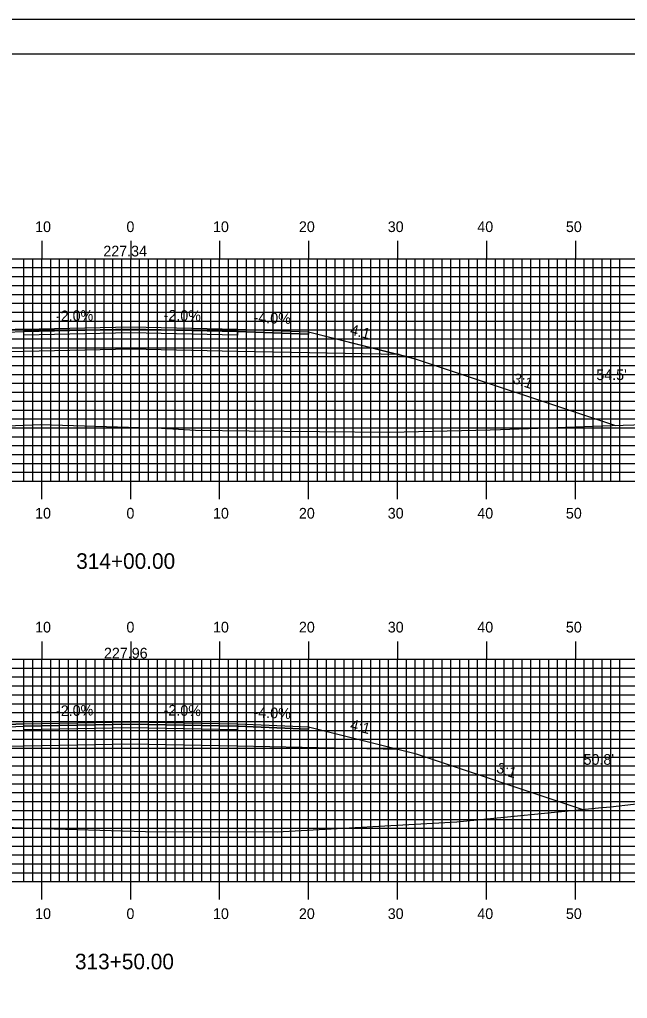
# Model space of a CAD drawing. Extents: x 1818850 to 1819194, y 442591 to 442811.
# Drawn here: x 1819003.7 to 1819072, y 442700.5 to 442810.5 of the extents above; entities that cross this region are included whole.
import ezdxf

# ---------------------------------------------------------------- set-up
doc = ezdxf.new("R2010")
doc.units = 0
for name, color, linetype in [('ANNOTATION', 7, 'Continuous'), ('BORDER', 7, 'Continuous'), ('D_Roadway_Centerline', 7, 'Continuous'), ('D_Roadway_Centerline_Text', 7, 'Continuous'), ('D_Roadway_Edge_Shoulder', 7, 'Continuous'), ('D_Roadway_Edge_TW', 7, 'Continuous'), ('D_Roadway_Pavement', 7, 'Continuous'), ('D_Roadway_SlopeLines', 7, 'Continuous'), ('D_Roadway_SubGrade', 7, 'Continuous'), ('D_Text_Standard', 7, 'Continuous'), ('H_V ANNOTATION', 7, 'Continuous'), ('MAJOR', 7, 'Continuous'), ('MINOR', 7, 'Continuous'), ('PLOT BOUNDARY', 7, 'Continuous'), ('S_Roadway_Centerline', 7, 'Continuous')]:
    doc.layers.add(name, color=color, linetype=linetype)

msp = doc.modelspace()

# ---------------------------------------------------------------- linework, layer by layer
at = {"layer": 'BORDER'}
msp.add_lwpolyline([(1818866.55, 442596.67), (1819186.55, 442596.67), (1819186.55, 442806.67), (1818866.55, 442806.67)], close=True, dxfattribs=at)
at = {"layer": 'D_Roadway_Centerline'}
for points in [[(1818961.68, 442764.95), (1818984.15, 442772.44), (1818985.98, 442772.9), (1818996.15, 442775.44), (1819004.15, 442775.76), (1819016.15, 442776), (1819028.15, 442775.76), (1819036.15, 442775.44), (1819046.33, 442772.9), (1819048.15, 442772.44), (1819070.66, 442764.94)], [(1818960.21, 442720.09), (1818984.15, 442728.07), (1818985.98, 442728.52), (1818996.15, 442731.07), (1819004.15, 442731.39), (1819016.15, 442731.63), (1819028.15, 442731.39), (1819036.15, 442731.07), (1819046.33, 442728.52), (1819048.15, 442728.07), (1819066.99, 442721.79)]]:
    msp.add_lwpolyline(points, dxfattribs=at)
at = {"layer": 'D_Roadway_Edge_Shoulder'}
for points in [[(1819004.15, 442775.76), (1818996.15, 442775.44), (1818996.15, 442775.19), (1819004.15, 442775.51)], [(1819028.15, 442775.76), (1819036.15, 442775.44), (1819036.15, 442775.19), (1819028.15, 442775.51)], [(1819004.15, 442731.39), (1818996.15, 442731.07), (1818996.15, 442730.82), (1819004.15, 442731.14)], [(1819028.15, 442731.39), (1819036.15, 442731.07), (1819036.15, 442730.82), (1819028.15, 442731.14)]]:
    msp.add_lwpolyline(points, close=True, dxfattribs=at)
at = {"layer": 'D_Roadway_Edge_TW'}
for points in [[(1819004.15, 442775.51), (1819004.15, 442775.76), (1819016.15, 442776), (1819028.15, 442775.76), (1819028.15, 442775.51), (1819016.15, 442775.75)], [(1819004.15, 442731.14), (1819004.15, 442731.39), (1819016.15, 442731.63), (1819028.15, 442731.39), (1819028.15, 442731.14), (1819016.15, 442731.38)]]:
    msp.add_lwpolyline(points, close=True, dxfattribs=at)
at = {"layer": 'D_Roadway_Pavement'}
for points in [[(1819004.15, 442775.09), (1819004.15, 442775.51), (1819016.15, 442775.75), (1819028.15, 442775.51), (1819028.15, 442775.09), (1819016.15, 442775.33)], [(1819004.15, 442730.72), (1819004.15, 442731.14), (1819016.15, 442731.38), (1819028.15, 442731.14), (1819028.15, 442730.72), (1819016.15, 442730.96)]]:
    msp.add_lwpolyline(points, close=True, dxfattribs=at)
at = {"layer": 'D_Roadway_SlopeLines'}
for points in [[(1819036.15, 442775.44), (1819048.15, 442772.44), (1819070.66, 442764.94)], [(1819036.15, 442731.07), (1819048.15, 442728.07), (1819066.99, 442721.79)]]:
    msp.add_lwpolyline(points, dxfattribs=at)
at = {"layer": 'D_Roadway_SubGrade'}
for points in [[(1819004.15, 442773.26), (1818985.98, 442772.9), (1818996.15, 442775.44), (1818996.15, 442775.19), (1819004.15, 442775.51), (1819016.15, 442775.75), (1819028.15, 442775.51), (1819036.15, 442775.19), (1819036.15, 442775.44), (1819046.33, 442772.9), (1819028.15, 442773.26), (1819016.15, 442773.5)], [(1819004.15, 442728.89), (1818985.98, 442728.52), (1818996.15, 442731.07), (1818996.15, 442730.82), (1819004.15, 442731.14), (1819016.15, 442731.38), (1819028.15, 442731.14), (1819036.15, 442730.82), (1819036.15, 442731.07), (1819046.33, 442728.52), (1819028.15, 442728.89), (1819016.15, 442729.13)]]:
    msp.add_lwpolyline(points, close=True, dxfattribs=at)
at = {"layer": 'MAJOR'}
for p, q in [((1819006.15, 442785.67), (1819006.15, 442783.67)), ((1819016.15, 442785.67), (1819016.15, 442783.67)), ((1819026.15, 442785.67), (1819026.15, 442783.67)), ((1819036.15, 442785.67), (1819036.15, 442783.67)), ((1819046.15, 442785.67), (1819046.15, 442783.67)), ((1819056.15, 442785.67), (1819056.15, 442783.67)), ((1819066.15, 442785.67), (1819066.15, 442783.67)), ((1818876.15, 442783.67), (1819156.15, 442783.67)), ((1818876.15, 442783.67), (1819156.15, 442783.67)), ((1819006.15, 442758.67), (1819006.15, 442783.67)), ((1819016.15, 442758.67), (1819016.15, 442783.67)), ((1819026.15, 442758.67), (1819026.15, 442783.67)), ((1819036.15, 442758.67), (1819036.15, 442783.67)), ((1819046.15, 442758.67), (1819046.15, 442783.67)), ((1819056.15, 442758.67), (1819056.15, 442783.67)), ((1819066.15, 442758.67), (1819066.15, 442783.67)), ((1818876.15, 442778.67), (1819156.15, 442778.67)), ((1818876.15, 442773.67), (1819156.15, 442773.67)), ((1818876.15, 442768.67), (1819156.15, 442768.67)), ((1818876.15, 442763.67), (1819156.15, 442763.67)), ((1818876.15, 442758.67), (1819156.15, 442758.67)), ((1818876.15, 442758.67), (1819156.15, 442758.67)), ((1819006.15, 442756.66), (1819006.15, 442758.67)), ((1819016.15, 442756.66), (1819016.15, 442758.67)), ((1819026.15, 442756.66), (1819026.15, 442758.67)), ((1819036.15, 442756.66), (1819036.15, 442758.67)), ((1819046.15, 442756.66), (1819046.15, 442758.67)), ((1819056.15, 442756.66), (1819056.15, 442758.67)), ((1819066.15, 442756.66), (1819066.15, 442758.67)), ((1819006.15, 442740.67), (1819006.15, 442738.67)), ((1819016.15, 442740.67), (1819016.15, 442738.67)), ((1819026.15, 442740.67), (1819026.15, 442738.67)), ((1819036.15, 442740.67), (1819036.15, 442738.67)), ((1819046.15, 442740.67), (1819046.15, 442738.67)), ((1819056.15, 442740.67), (1819056.15, 442738.67)), ((1819066.15, 442740.67), (1819066.15, 442738.67)), ((1818876.15, 442738.67), (1819156.15, 442738.67)), ((1818876.15, 442738.67), (1819156.15, 442738.67)), ((1819006.15, 442713.67), (1819006.15, 442738.67)), ((1819016.15, 442713.67), (1819016.15, 442738.67)), ((1819026.15, 442713.67), (1819026.15, 442738.67)), ((1819036.15, 442713.67), (1819036.15, 442738.67)), ((1819046.15, 442713.67), (1819046.15, 442738.67)), ((1819056.15, 442713.67), (1819056.15, 442738.67)), ((1819066.15, 442713.67), (1819066.15, 442738.67)), ((1818876.15, 442733.67), (1819156.15, 442733.67)), ((1818876.15, 442728.67), (1819156.15, 442728.67)), ((1818876.15, 442723.67), (1819156.15, 442723.67)), ((1818876.15, 442718.67), (1819156.15, 442718.67)), ((1818876.15, 442713.67), (1819156.15, 442713.67)), ((1818876.15, 442713.67), (1819156.15, 442713.67)), ((1819006.15, 442711.66), (1819006.15, 442713.67)), ((1819016.15, 442711.66), (1819016.15, 442713.67)), ((1819026.15, 442711.66), (1819026.15, 442713.67)), ((1819036.15, 442711.66), (1819036.15, 442713.67)), ((1819046.15, 442711.66), (1819046.15, 442713.67)), ((1819056.15, 442711.66), (1819056.15, 442713.67)), ((1819066.15, 442711.66), (1819066.15, 442713.67))]:
    msp.add_line(p, q, dxfattribs=at)
at = {"layer": 'MINOR'}
for p, q in [((1819004.15, 442758.67), (1819004.15, 442783.67)), ((1819005.15, 442758.67), (1819005.15, 442783.67)), ((1819007.15, 442758.67), (1819007.15, 442783.67)), ((1819008.15, 442758.67), (1819008.15, 442783.67)), ((1819009.15, 442758.67), (1819009.15, 442783.67)), ((1819010.15, 442758.67), (1819010.15, 442783.67)), ((1819011.15, 442758.67), (1819011.15, 442783.67)), ((1819012.15, 442758.67), (1819012.15, 442783.67)), ((1819013.15, 442758.67), (1819013.15, 442783.67)), ((1819014.15, 442758.67), (1819014.15, 442783.67)), ((1819015.15, 442758.67), (1819015.15, 442783.67)), ((1819017.15, 442758.67), (1819017.15, 442783.67)), ((1819018.15, 442758.67), (1819018.15, 442783.67)), ((1819019.15, 442758.67), (1819019.15, 442783.67)), ((1819020.15, 442758.67), (1819020.15, 442783.67)), ((1819021.15, 442758.67), (1819021.15, 442783.67)), ((1819022.15, 442758.67), (1819022.15, 442783.67)), ((1819023.15, 442758.67), (1819023.15, 442783.67)), ((1819024.15, 442758.67), (1819024.15, 442783.67)), ((1819025.15, 442758.67), (1819025.15, 442783.67)), ((1819027.15, 442758.67), (1819027.15, 442783.67)), ((1819028.15, 442758.67), (1819028.15, 442783.67)), ((1819029.15, 442758.67), (1819029.15, 442783.67)), ((1819030.15, 442758.67), (1819030.15, 442783.67)), ((1819031.15, 442758.67), (1819031.15, 442783.67)), ((1819032.15, 442758.67), (1819032.15, 442783.67)), ((1819033.15, 442758.67), (1819033.15, 442783.67)), ((1819034.15, 442758.67), (1819034.15, 442783.67)), ((1819035.15, 442758.67), (1819035.15, 442783.67)), ((1819037.15, 442758.67), (1819037.15, 442783.67)), ((1819038.15, 442758.67), (1819038.15, 442783.67)), ((1819039.15, 442758.67), (1819039.15, 442783.67)), ((1819040.15, 442758.67), (1819040.15, 442783.67)), ((1819041.15, 442758.67), (1819041.15, 442783.67)), ((1819042.15, 442758.67), (1819042.15, 442783.67)), ((1819043.15, 442758.67), (1819043.15, 442783.67)), ((1819044.15, 442758.67), (1819044.15, 442783.67)), ((1819045.15, 442758.67), (1819045.15, 442783.67)), ((1819047.15, 442758.67), (1819047.15, 442783.67)), ((1819048.15, 442758.67), (1819048.15, 442783.67)), ((1819049.15, 442758.67), (1819049.15, 442783.67)), ((1819050.15, 442758.67), (1819050.15, 442783.67)), ((1819051.15, 442758.67), (1819051.15, 442783.67)), ((1819052.15, 442758.67), (1819052.15, 442783.67)), ((1819053.15, 442758.67), (1819053.15, 442783.67)), ((1819054.15, 442758.67), (1819054.15, 442783.67)), ((1819055.15, 442758.67), (1819055.15, 442783.67)), ((1819057.15, 442758.67), (1819057.15, 442783.67)), ((1819058.15, 442758.67), (1819058.15, 442783.67)), ((1819059.15, 442758.67), (1819059.15, 442783.67)), ((1819060.15, 442758.67), (1819060.15, 442783.67)), ((1819061.15, 442758.67), (1819061.15, 442783.67)), ((1819062.15, 442758.67), (1819062.15, 442783.67)), ((1819063.15, 442758.67), (1819063.15, 442783.67)), ((1819064.15, 442758.67), (1819064.15, 442783.67)), ((1819065.15, 442758.67), (1819065.15, 442783.67)), ((1819067.15, 442758.67), (1819067.15, 442783.67)), ((1819068.15, 442758.67), (1819068.15, 442783.67)), ((1819069.15, 442758.67), (1819069.15, 442783.67)), ((1819070.15, 442758.67), (1819070.15, 442783.67)), ((1819071.15, 442758.67), (1819071.15, 442783.67)), ((1818876.15, 442782.67), (1819156.15, 442782.67)), ((1818876.15, 442781.67), (1819156.15, 442781.67)), ((1818876.15, 442780.67), (1819156.15, 442780.67)), ((1818876.15, 442779.67), (1819156.15, 442779.67)), ((1818876.15, 442777.67), (1819156.15, 442777.67)), ((1818876.15, 442776.67), (1819156.15, 442776.67)), ((1818876.15, 442775.67), (1819156.15, 442775.67)), ((1818876.15, 442774.67), (1819156.15, 442774.67)), ((1818876.15, 442772.67), (1819156.15, 442772.67)), ((1818876.15, 442771.67), (1819156.15, 442771.67)), ((1818876.15, 442770.67), (1819156.15, 442770.67)), ((1818876.15, 442769.67), (1819156.15, 442769.67)), ((1818876.15, 442767.67), (1819156.15, 442767.67)), ((1818876.15, 442766.67), (1819156.15, 442766.67)), ((1818876.15, 442765.67), (1819156.15, 442765.67)), ((1818876.15, 442764.67), (1819156.15, 442764.67)), ((1818876.15, 442762.67), (1819156.15, 442762.67)), ((1818876.15, 442761.67), (1819156.15, 442761.67)), ((1818876.15, 442760.67), (1819156.15, 442760.67)), ((1818876.15, 442759.67), (1819156.15, 442759.67)), ((1819004.15, 442713.67), (1819004.15, 442738.67)), ((1819005.15, 442713.67), (1819005.15, 442738.67)), ((1819007.15, 442713.67), (1819007.15, 442738.67)), ((1819008.15, 442713.67), (1819008.15, 442738.67)), ((1819009.15, 442713.67), (1819009.15, 442738.67)), ((1819010.15, 442713.67), (1819010.15, 442738.67)), ((1819011.15, 442713.67), (1819011.15, 442738.67)), ((1819012.15, 442713.67), (1819012.15, 442738.67)), ((1819013.15, 442713.67), (1819013.15, 442738.67)), ((1819014.15, 442713.67), (1819014.15, 442738.67)), ((1819015.15, 442713.67), (1819015.15, 442738.67)), ((1819017.15, 442713.67), (1819017.15, 442738.67)), ((1819018.15, 442713.67), (1819018.15, 442738.67)), ((1819019.15, 442713.67), (1819019.15, 442738.67)), ((1819020.15, 442713.67), (1819020.15, 442738.67)), ((1819021.15, 442713.67), (1819021.15, 442738.67)), ((1819022.15, 442713.67), (1819022.15, 442738.67)), ((1819023.15, 442713.67), (1819023.15, 442738.67)), ((1819024.15, 442713.67), (1819024.15, 442738.67)), ((1819025.15, 442713.67), (1819025.15, 442738.67)), ((1819027.15, 442713.67), (1819027.15, 442738.67)), ((1819028.15, 442713.67), (1819028.15, 442738.67)), ((1819029.15, 442713.67), (1819029.15, 442738.67)), ((1819030.15, 442713.67), (1819030.15, 442738.67)), ((1819031.15, 442713.67), (1819031.15, 442738.67)), ((1819032.15, 442713.67), (1819032.15, 442738.67)), ((1819033.15, 442713.67), (1819033.15, 442738.67)), ((1819034.15, 442713.67), (1819034.15, 442738.67)), ((1819035.15, 442713.67), (1819035.15, 442738.67)), ((1819037.15, 442713.67), (1819037.15, 442738.67)), ((1819038.15, 442713.67), (1819038.15, 442738.67)), ((1819039.15, 442713.67), (1819039.15, 442738.67)), ((1819040.15, 442713.67), (1819040.15, 442738.67)), ((1819041.15, 442713.67), (1819041.15, 442738.67)), ((1819042.15, 442713.67), (1819042.15, 442738.67)), ((1819043.15, 442713.67), (1819043.15, 442738.67)), ((1819044.15, 442713.67), (1819044.15, 442738.67)), ((1819045.15, 442713.67), (1819045.15, 442738.67)), ((1819047.15, 442713.67), (1819047.15, 442738.67)), ((1819048.15, 442713.67), (1819048.15, 442738.67)), ((1819049.15, 442713.67), (1819049.15, 442738.67)), ((1819050.15, 442713.67), (1819050.15, 442738.67)), ((1819051.15, 442713.67), (1819051.15, 442738.67)), ((1819052.15, 442713.67), (1819052.15, 442738.67)), ((1819053.15, 442713.67), (1819053.15, 442738.67)), ((1819054.15, 442713.67), (1819054.15, 442738.67)), ((1819055.15, 442713.67), (1819055.15, 442738.67)), ((1819057.15, 442713.67), (1819057.15, 442738.67)), ((1819058.15, 442713.67), (1819058.15, 442738.67)), ((1819059.15, 442713.67), (1819059.15, 442738.67)), ((1819060.15, 442713.67), (1819060.15, 442738.67)), ((1819061.15, 442713.67), (1819061.15, 442738.67)), ((1819062.15, 442713.67), (1819062.15, 442738.67)), ((1819063.15, 442713.67), (1819063.15, 442738.67)), ((1819064.15, 442713.67), (1819064.15, 442738.67)), ((1819065.15, 442713.67), (1819065.15, 442738.67)), ((1819067.15, 442713.67), (1819067.15, 442738.67)), ((1819068.15, 442713.67), (1819068.15, 442738.67)), ((1819069.15, 442713.67), (1819069.15, 442738.67)), ((1819070.15, 442713.67), (1819070.15, 442738.67)), ((1819071.15, 442713.67), (1819071.15, 442738.67)), ((1818876.15, 442737.67), (1819156.15, 442737.67)), ((1818876.15, 442736.67), (1819156.15, 442736.67)), ((1818876.15, 442735.67), (1819156.15, 442735.67)), ((1818876.15, 442734.67), (1819156.15, 442734.67)), ((1818876.15, 442732.67), (1819156.15, 442732.67)), ((1818876.15, 442731.67), (1819156.15, 442731.67)), ((1818876.15, 442730.67), (1819156.15, 442730.67)), ((1818876.15, 442729.67), (1819156.15, 442729.67)), ((1818876.15, 442727.67), (1819156.15, 442727.67)), ((1818876.15, 442726.67), (1819156.15, 442726.67)), ((1818876.15, 442725.67), (1819156.15, 442725.67)), ((1818876.15, 442724.67), (1819156.15, 442724.67)), ((1818876.15, 442722.67), (1819156.15, 442722.67)), ((1818876.15, 442721.67), (1819156.15, 442721.67)), ((1818876.15, 442720.67), (1819156.15, 442720.67)), ((1818876.15, 442719.67), (1819156.15, 442719.67)), ((1818876.15, 442717.67), (1819156.15, 442717.67)), ((1818876.15, 442716.67), (1819156.15, 442716.67)), ((1818876.15, 442715.67), (1819156.15, 442715.67)), ((1818876.15, 442714.67), (1819156.15, 442714.67))]:
    msp.add_line(p, q, dxfattribs=at)
at = {"layer": 'PLOT BOUNDARY'}
msp.add_lwpolyline([(1818850.36, 442590.55), (1819190.36, 442590.55), (1819190.36, 442810.55), (1818850.36, 442810.55)], close=True, dxfattribs=at)
at = {"layer": 'S_Roadway_Centerline'}
for points in [[(1818939.64, 442764.62), (1818954.8, 442764.81), (1818964.64, 442765.01), (1818972.42, 442764.82), (1818983.45, 442764.59), (1818992.8, 442764.53), (1819006, 442765.06), (1819019.6, 442764.63), (1819023.44, 442764.42), (1819029.47, 442764.33), (1819045.29, 442764.18), (1819056.55, 442764.44), (1819057.72, 442764.47), (1819070.3, 442764.93), (1819073.96, 442765.06)], [(1818876.15, 442719.62), (1818884.53, 442719.84), (1818887.7, 442719.84), (1818900.44, 442719.94), (1818909.33, 442720), (1818923.1, 442719.99), (1818940.8, 442720.11), (1818948.93, 442720.12), (1818952.95, 442720.12), (1818967.5, 442720.05), (1818976.8, 442719.99), (1818985.17, 442719.89), (1819001.76, 442719.77), (1819002.98, 442719.77), (1819004.96, 442719.69), (1819017.83, 442719.31), (1819032.61, 442719.27), (1819052.82, 442720.41), (1819068.74, 442721.96), (1819070.09, 442722.09), (1819098.53, 442725.38)]]:
    msp.add_lwpolyline(points, dxfattribs=at)

# ---------------------------------------------------------------- texts
at = {"layer": 'ANNOTATION'}
for s, rotation, p in [('-2.0%', 1.1458, (1819007.76, 442776.63)), ('-2.0%', 358.8542, (1819019.84, 442776.73)), ('-4.0%', 357.7094, (1819029.94, 442776.49)), ('4:1', 345.9638, (1819040.74, 442775.16)), ('3:1', 341.5652, (1819059.01, 442769.73)), ('-2.0%', 1.1458, (1819007.76, 442732.26)), ('-2.0%', 358.8542, (1819019.84, 442732.35)), ('-4.0%', 357.7094, (1819029.94, 442732.12)), ('4:1', 345.9638, (1819040.74, 442730.78)), ('3:1', 341.5652, (1819057.17, 442725.97))]:
    msp.add_text(s, height=1.2, rotation=rotation, dxfattribs=at).set_placement(p)
at = {"layer": 'D_Roadway_Centerline'}
for s, p in [('C', (1819016.15, 442776)), ('L', (1819016.15, 442775.99)), ('C', (1819016.15, 442731.63)), ('L', (1819016.15, 442731.62))]:
    msp.add_text(s, height=0.0146, dxfattribs=at).set_placement(p)
at = {"layer": 'D_Roadway_Centerline_Text'}
for s, p in [('227.34', (1819013.07, 442783.93)), ('227.96', (1819013.14, 442738.75))]:
    msp.add_text(s, height=1.2, dxfattribs=at).set_placement(p)
at = {"layer": 'D_Text_Standard'}
for s, p in [("54.5'", (1819068.5, 442770.03)), ("50.8'", (1819067.07, 442726.8))]:
    msp.add_text(s, height=1.2, dxfattribs=at).set_placement(p)
at = {"layer": 'H_V ANNOTATION'}
for s, height, p in [('10', 1.2, (1819005.4, 442786.67)), ('0', 1.2, (1819015.67, 442786.67)), ('10', 1.2, (1819025.4, 442786.67)), ('20', 1.2, (1819035.06, 442786.67)), ('30', 1.2, (1819045.05, 442786.67)), ('40', 1.2, (1819055.12, 442786.67)), ('50', 1.2, (1819065.08, 442786.67)), ('10', 1.2, (1819005.4, 442754.47)), ('0', 1.2, (1819015.67, 442754.47)), ('10', 1.2, (1819025.4, 442754.47)), ('20', 1.2, (1819035.06, 442754.47)), ('30', 1.2, (1819045.05, 442754.47)), ('40', 1.2, (1819055.12, 442754.47)), ('50', 1.2, (1819065.08, 442754.47)), ('314+00.00', 1.75, (1819010.02, 442748.82)), ('10', 1.2, (1819005.4, 442741.67)), ('0', 1.2, (1819015.67, 442741.67)), ('10', 1.2, (1819025.4, 442741.67)), ('20', 1.2, (1819035.06, 442741.67)), ('30', 1.2, (1819045.05, 442741.67)), ('40', 1.2, (1819055.12, 442741.67)), ('50', 1.2, (1819065.08, 442741.67)), ('10', 1.2, (1819005.4, 442709.47)), ('0', 1.2, (1819015.67, 442709.47)), ('10', 1.2, (1819025.4, 442709.47)), ('20', 1.2, (1819035.06, 442709.47)), ('30', 1.2, (1819045.05, 442709.47)), ('40', 1.2, (1819055.12, 442709.47)), ('50', 1.2, (1819065.08, 442709.47)), ('313+50.00', 1.75, (1819009.88, 442703.82))]:
    msp.add_text(s, height=height, dxfattribs=at).set_placement(p)

doc.saveas('drawing.dxf')
